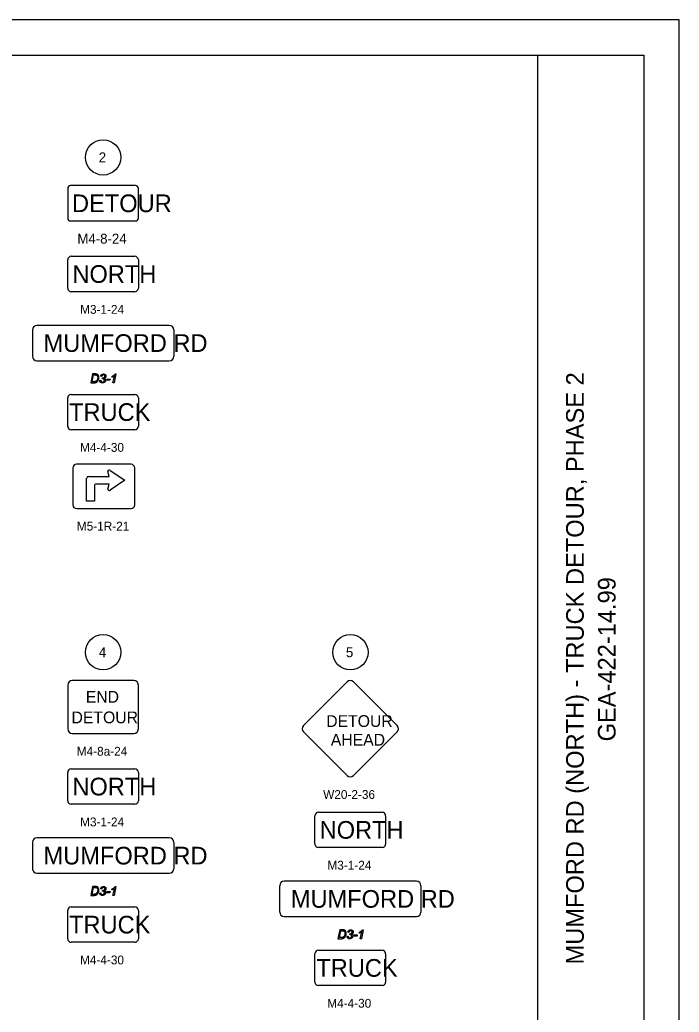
# Model space of a CAD drawing. Extents: x -0.3 to 34, y 0 to 22.
# Drawn here: x 24.67 to 34, y 7.96 to 22 of the extents above; entities that cross this region are included whole.
import ezdxf

# ---------------------------------------------------------------- set-up
doc = ezdxf.new("R2010")
doc.units = 0
for name, color, linetype in [('GM_X_County', 7, 'Continuous'), ('GM_X_Minor_Lake_Text', 7, 'Continuous'), ('GM_X_Minor_River_Text', 7, 'Continuous'), ('GM_X_Section', 7, 'Continuous'), ('GM_X_Township', 7, 'Continuous')]:
    doc.layers.add(name, color=color, linetype=linetype)

msp = doc.modelspace()

# ---------------------------------------------------------------- linework, layer by layer
at = {"layer": 'GM_X_County'}
msp.add_line((32, 0.5), (32, 21.5), dxfattribs=at)
msp.add_lwpolyline([(1.5, 21.5), (33.5, 21.5), (33.5, 0.5), (1.5, 0.5)], close=True, dxfattribs=at)
at = {"layer": 'GM_X_Minor_Lake_Text'}
for p, q in [((25.798, 16.899), (25.813, 16.901)), ((25.827, 16.956), (25.812, 16.959)), ((25.836, 16.924), (25.839, 16.937)), ((25.97, 16.944), (25.973, 16.958)), ((25.827, 9.706), (25.812, 9.709)), ((25.836, 9.674), (25.839, 9.687)), ((25.97, 9.694), (25.973, 9.708)), ((25.798, 9.649), (25.813, 9.651)), ((29.298, 9.036), (29.313, 9.038)), ((29.327, 9.094), (29.312, 9.097)), ((29.336, 9.061), (29.339, 9.074)), ((29.47, 9.082), (29.473, 9.096))]:
    msp.add_line(p, q, dxfattribs=at)
for points in [[(25.734, 16.991), (25.697, 16.991), (25.67, 16.866), (25.716, 16.866)], [(26.019, 16.991), (26.028, 16.991), (26.002, 16.866), (25.986, 16.866), (26.006, 16.96)], [(25.71, 16.88), (25.69, 16.88), (25.71, 16.977), (25.732, 16.977)], [(25.734, 9.741), (25.697, 9.741), (25.67, 9.616), (25.716, 9.616)], [(25.71, 9.63), (25.69, 9.63), (25.71, 9.727), (25.732, 9.727)], [(26.019, 9.741), (26.028, 9.741), (26.002, 9.616), (25.986, 9.616), (26.006, 9.71)], [(29.234, 9.128), (29.197, 9.128), (29.17, 9.003), (29.216, 9.003)], [(29.519, 9.129), (29.528, 9.129), (29.502, 9.003), (29.486, 9.003), (29.506, 9.098)], [(29.21, 9.018), (29.19, 9.018), (29.21, 9.114), (29.232, 9.114)]]:
    msp.add_lwpolyline(points, dxfattribs=at)
for points in [[(25.894, 16.903), (25.897, 16.919), (25.944, 16.919), (25.941, 16.903)], [(25.894, 9.653), (25.897, 9.669), (25.944, 9.669), (25.941, 9.653)], [(29.394, 9.041), (29.397, 9.056), (29.444, 9.056), (29.441, 9.041)]]:
    msp.add_lwpolyline(points, close=True, dxfattribs=at)
for centre in [(25.846, 20.055), (25.846, 13.055), (29.346, 13.055)]:
    msp.add_circle(centre, 0.25, dxfattribs=at)
for points in [[(25.755, 16.989), (25.748, 16.991), (25.734, 16.991)], [(25.772, 16.98), (25.765, 16.986), (25.755, 16.989)], [(25.827, 16.983), (25.837, 16.991), (25.852, 16.991)], [(25.852, 16.991), (25.867, 16.991), (25.877, 16.982)], [(26.012, 16.983), (26.016, 16.987), (26.019, 16.991)], [(25.734, 16.883), (25.723, 16.88), (25.71, 16.88)], [(25.716, 16.866), (25.728, 16.866), (25.736, 16.868)], [(25.732, 16.977), (25.745, 16.977), (25.751, 16.975)], [(25.745, 16.887), (25.74, 16.884), (25.734, 16.883)], [(25.736, 16.868), (25.747, 16.87), (25.755, 16.876)], [(25.756, 16.897), (25.751, 16.891), (25.745, 16.887)], [(25.751, 16.975), (25.76, 16.972), (25.765, 16.964)], [(25.755, 16.876), (25.763, 16.881), (25.771, 16.891)], [(25.766, 16.916), (25.762, 16.906), (25.756, 16.897)], [(25.765, 16.964), (25.77, 16.956), (25.77, 16.941)], [(25.77, 16.941), (25.77, 16.927), (25.766, 16.916)], [(25.771, 16.891), (25.778, 16.9), (25.783, 16.912)], [(25.783, 16.963), (25.78, 16.973), (25.772, 16.98)], [(25.787, 16.94), (25.787, 16.952), (25.783, 16.963)], [(25.783, 16.912), (25.787, 16.925), (25.787, 16.94)], [(25.81, 16.873), (25.8, 16.883), (25.798, 16.899)], [(25.837, 16.864), (25.82, 16.864), (25.81, 16.873)], [(25.812, 16.959), (25.816, 16.974), (25.827, 16.983)], [(25.813, 16.901), (25.815, 16.887), (25.821, 16.882)], [(25.821, 16.882), (25.827, 16.876), (25.836, 16.876)], [(25.836, 16.973), (25.829, 16.967), (25.827, 16.956)], [(25.851, 16.979), (25.842, 16.979), (25.836, 16.973)], [(25.841, 16.924), (25.84, 16.924), (25.836, 16.924)], [(25.836, 16.876), (25.848, 16.876), (25.856, 16.884)], [(25.868, 16.876), (25.855, 16.864), (25.837, 16.864)], [(25.839, 16.937), (25.841, 16.936), (25.843, 16.936)], [(25.858, 16.918), (25.852, 16.924), (25.841, 16.924)], [(25.843, 16.936), (25.856, 16.936), (25.864, 16.943)], [(25.865, 16.973), (25.859, 16.979), (25.851, 16.979)], [(25.856, 16.884), (25.864, 16.892), (25.864, 16.903)], [(25.864, 16.903), (25.864, 16.912), (25.858, 16.918)], [(25.864, 16.943), (25.871, 16.949), (25.871, 16.959)], [(25.871, 16.959), (25.871, 16.967), (25.865, 16.973)], [(25.881, 16.942), (25.876, 16.935), (25.865, 16.93)], [(25.865, 16.93), (25.873, 16.925), (25.876, 16.919)], [(25.88, 16.905), (25.88, 16.888), (25.868, 16.876)], [(25.876, 16.919), (25.88, 16.913), (25.88, 16.905)], [(25.877, 16.982), (25.886, 16.973), (25.886, 16.959)], [(25.886, 16.959), (25.886, 16.949), (25.881, 16.942)], [(26.006, 16.96), (25.993, 16.95), (25.97, 16.944)], [(25.973, 16.958), (25.984, 16.963), (25.995, 16.97)], [(25.995, 16.97), (26.007, 16.978), (26.012, 16.983)], [(25.732, 9.727), (25.745, 9.727), (25.751, 9.725)], [(25.755, 9.739), (25.748, 9.741), (25.734, 9.741)], [(25.751, 9.725), (25.76, 9.722), (25.765, 9.714)], [(25.772, 9.73), (25.765, 9.736), (25.755, 9.739)], [(25.765, 9.714), (25.77, 9.706), (25.77, 9.691)], [(25.77, 9.691), (25.77, 9.677), (25.766, 9.666)], [(25.783, 9.713), (25.78, 9.723), (25.772, 9.73)], [(25.787, 9.69), (25.787, 9.702), (25.783, 9.713)], [(25.783, 9.662), (25.787, 9.675), (25.787, 9.69)], [(25.812, 9.709), (25.816, 9.724), (25.827, 9.733)], [(25.827, 9.733), (25.837, 9.741), (25.852, 9.741)], [(25.836, 9.723), (25.829, 9.717), (25.827, 9.706)], [(25.851, 9.729), (25.842, 9.729), (25.836, 9.723)], [(25.839, 9.687), (25.841, 9.686), (25.843, 9.686)], [(25.843, 9.686), (25.856, 9.686), (25.864, 9.693)], [(25.865, 9.723), (25.859, 9.729), (25.851, 9.729)], [(25.852, 9.741), (25.867, 9.741), (25.877, 9.732)], [(25.864, 9.693), (25.871, 9.699), (25.871, 9.709)], [(25.871, 9.709), (25.871, 9.717), (25.865, 9.723)], [(25.881, 9.692), (25.876, 9.685), (25.865, 9.68)], [(25.877, 9.732), (25.886, 9.723), (25.886, 9.709)], [(25.886, 9.709), (25.886, 9.699), (25.881, 9.692)], [(26.006, 9.71), (25.993, 9.7), (25.97, 9.694)], [(25.973, 9.708), (25.984, 9.713), (25.995, 9.72)], [(25.995, 9.72), (26.007, 9.728), (26.012, 9.733)], [(26.012, 9.733), (26.016, 9.737), (26.019, 9.741)], [(25.734, 9.633), (25.723, 9.63), (25.71, 9.63)], [(25.716, 9.616), (25.728, 9.616), (25.736, 9.618)], [(25.745, 9.637), (25.74, 9.634), (25.734, 9.633)], [(25.736, 9.618), (25.747, 9.62), (25.755, 9.626)], [(25.756, 9.647), (25.751, 9.641), (25.745, 9.637)], [(25.755, 9.626), (25.763, 9.631), (25.771, 9.641)], [(25.766, 9.666), (25.762, 9.656), (25.756, 9.647)], [(25.771, 9.641), (25.778, 9.65), (25.783, 9.662)], [(25.81, 9.623), (25.8, 9.633), (25.798, 9.649)], [(25.837, 9.614), (25.82, 9.614), (25.81, 9.623)], [(25.813, 9.651), (25.815, 9.637), (25.821, 9.632)], [(25.821, 9.632), (25.827, 9.626), (25.836, 9.626)], [(25.841, 9.674), (25.84, 9.674), (25.836, 9.674)], [(25.836, 9.626), (25.848, 9.626), (25.856, 9.634)], [(25.868, 9.626), (25.855, 9.614), (25.837, 9.614)], [(25.858, 9.668), (25.852, 9.674), (25.841, 9.674)], [(25.856, 9.634), (25.864, 9.642), (25.864, 9.653)], [(25.864, 9.653), (25.864, 9.662), (25.858, 9.668)], [(25.865, 9.68), (25.873, 9.675), (25.876, 9.669)], [(25.88, 9.655), (25.88, 9.638), (25.868, 9.626)], [(25.876, 9.669), (25.88, 9.663), (25.88, 9.655)], [(29.255, 9.127), (29.248, 9.128), (29.234, 9.128)], [(29.272, 9.117), (29.265, 9.124), (29.255, 9.127)], [(29.327, 9.121), (29.337, 9.129), (29.352, 9.129)], [(29.352, 9.129), (29.367, 9.129), (29.377, 9.12)], [(29.512, 9.121), (29.516, 9.124), (29.519, 9.129)], [(29.234, 9.02), (29.223, 9.018), (29.21, 9.018)], [(29.216, 9.003), (29.228, 9.003), (29.236, 9.005)], [(29.232, 9.114), (29.245, 9.114), (29.251, 9.112)], [(29.245, 9.025), (29.24, 9.022), (29.234, 9.02)], [(29.236, 9.005), (29.247, 9.008), (29.255, 9.013)], [(29.256, 9.035), (29.251, 9.028), (29.245, 9.025)], [(29.251, 9.112), (29.26, 9.11), (29.265, 9.102)], [(29.255, 9.013), (29.263, 9.019), (29.271, 9.028)], [(29.266, 9.054), (29.262, 9.043), (29.256, 9.035)], [(29.265, 9.102), (29.27, 9.093), (29.27, 9.078)], [(29.27, 9.078), (29.27, 9.065), (29.266, 9.054)], [(29.271, 9.028), (29.278, 9.037), (29.283, 9.05)], [(29.283, 9.1), (29.28, 9.11), (29.272, 9.117)], [(29.287, 9.077), (29.287, 9.09), (29.283, 9.1)], [(29.283, 9.05), (29.287, 9.062), (29.287, 9.077)], [(29.31, 9.011), (29.3, 9.02), (29.298, 9.036)], [(29.337, 9.001), (29.32, 9.001), (29.31, 9.011)], [(29.312, 9.097), (29.316, 9.112), (29.327, 9.121)], [(29.313, 9.038), (29.315, 9.025), (29.321, 9.019)], [(29.321, 9.019), (29.327, 9.014), (29.336, 9.014)], [(29.336, 9.111), (29.329, 9.105), (29.327, 9.094)], [(29.351, 9.117), (29.342, 9.117), (29.336, 9.111)], [(29.341, 9.062), (29.34, 9.062), (29.336, 9.061)], [(29.336, 9.014), (29.348, 9.014), (29.356, 9.022)], [(29.368, 9.014), (29.355, 9.001), (29.337, 9.001)], [(29.339, 9.074), (29.341, 9.074), (29.343, 9.074)], [(29.358, 9.056), (29.352, 9.062), (29.341, 9.062)], [(29.343, 9.074), (29.356, 9.074), (29.364, 9.08)], [(29.365, 9.111), (29.359, 9.117), (29.351, 9.117)], [(29.356, 9.022), (29.364, 9.03), (29.364, 9.041)], [(29.364, 9.041), (29.364, 9.05), (29.358, 9.056)], [(29.364, 9.08), (29.371, 9.087), (29.371, 9.096)], [(29.371, 9.096), (29.371, 9.105), (29.365, 9.111)], [(29.381, 9.08), (29.376, 9.072), (29.365, 9.067)], [(29.365, 9.067), (29.373, 9.063), (29.376, 9.057)], [(29.38, 9.043), (29.38, 9.026), (29.368, 9.014)], [(29.376, 9.057), (29.38, 9.051), (29.38, 9.043)], [(29.377, 9.12), (29.386, 9.11), (29.386, 9.097)], [(29.386, 9.097), (29.386, 9.087), (29.381, 9.08)], [(29.506, 9.098), (29.493, 9.088), (29.47, 9.082)], [(29.473, 9.096), (29.484, 9.1), (29.495, 9.108)], [(29.495, 9.108), (29.507, 9.115), (29.512, 9.121)]]:
    msp.add_open_spline(points, degree=2, dxfattribs=at)
at = {"layer": 'GM_X_Minor_River_Text'}
for p, q in [((25.345, 18.205), (25.345, 18.605)), ((25.395, 18.655), (26.295, 18.655)), ((26.345, 18.605), (26.345, 18.205)), ((26.295, 18.155), (25.395, 18.155)), ((25.345, 16.252), (25.345, 16.652)), ((25.395, 16.702), (26.295, 16.702)), ((26.345, 16.652), (26.345, 16.252)), ((26.295, 16.202), (25.395, 16.202)), ((25.418, 15.663), (25.418, 15.138)), ((26.243, 15.713), (25.468, 15.713)), ((25.934, 15.541), (25.913, 15.612)), ((25.948, 15.626), (26.152, 15.487)), ((26.293, 15.138), (26.293, 15.663)), ((25.613, 15.19), (25.613, 15.518)), ((25.637, 15.541), (25.934, 15.541)), ((25.637, 15.541), (25.637, 15.541)), ((26.152, 15.487), (25.948, 15.347)), ((25.723, 15.416), (25.723, 15.19)), ((25.934, 15.432), (25.738, 15.432)), ((25.913, 15.362), (25.934, 15.432)), ((25.723, 15.19), (25.613, 15.19)), ((25.468, 15.088), (26.243, 15.088)), ((25.395, 11.405), (26.295, 11.405)), ((25.345, 10.955), (25.345, 11.355)), ((26.345, 11.355), (26.345, 10.955)), ((26.295, 10.905), (25.395, 10.905)), ((28.845, 10.342), (28.845, 10.742)), ((28.895, 10.792), (29.795, 10.792)), ((29.845, 10.742), (29.845, 10.342)), ((29.795, 10.292), (28.895, 10.292)), ((25.395, 9.452), (26.295, 9.452)), ((25.345, 9.002), (25.345, 9.402)), ((26.345, 9.402), (26.345, 9.002)), ((26.295, 8.952), (25.395, 8.952)), ((28.845, 8.39), (28.845, 8.79)), ((28.895, 8.84), (29.795, 8.84)), ((29.845, 8.79), (29.845, 8.39)), ((29.795, 8.34), (28.895, 8.34))]:
    msp.add_line(p, q, dxfattribs=at)
for points in [[(26.305, 19.655), (25.385, 19.655)], [(25.345, 19.615), (25.345, 19.195)], [(26.345, 19.195), (26.345, 19.615)], [(25.385, 19.155), (26.305, 19.155)], [(24.845, 17.616), (24.845, 17.241)], [(26.783, 17.678), (24.908, 17.678)], [(26.845, 17.616), (26.845, 17.241)], [(24.908, 17.178), (26.783, 17.178)], [(26.28, 12.655), (25.41, 12.655)], [(28.682, 12.018), (29.301, 12.636)], [(29.389, 12.636), (30.008, 12.018)], [(25.345, 12.59), (25.345, 11.97)], [(26.345, 11.97), (26.345, 12.59)], [(25.41, 11.905), (26.28, 11.905)], [(29.301, 11.311), (28.682, 11.929)], [(30.008, 11.929), (29.389, 11.311)], [(26.783, 10.428), (24.908, 10.428)], [(24.845, 10.366), (24.845, 9.991)], [(26.845, 10.366), (26.845, 9.991)], [(24.908, 9.928), (26.783, 9.928)], [(28.345, 9.753), (28.345, 9.378)], [(30.283, 9.816), (28.408, 9.816)], [(30.345, 9.753), (30.345, 9.378)], [(28.408, 9.316), (30.283, 9.316)]]:
    msp.add_lwpolyline(points, dxfattribs=at)
for centre, radius, start, end in [((25.385, 19.615), 0.04, 90, 180), ((26.305, 19.615), 0.04, 0, 90), ((25.385, 19.195), 0.04, 180, 270), ((26.305, 19.195), 0.04, 270, 0), ((25.395, 18.605), 0.05, 90, 180), ((26.295, 18.605), 0.05, 0, 90), ((25.395, 18.205), 0.05, 180, 270), ((26.295, 18.205), 0.05, 270, 0), ((24.908, 17.616), 0.0625, 90, 180), ((26.783, 17.616), 0.0625, 0, 90), ((24.908, 17.241), 0.0625, 180, 270), ((26.783, 17.241), 0.0625, 270, 0), ((25.395, 16.652), 0.05, 90, 180), ((26.295, 16.652), 0.05, 0, 90), ((25.395, 16.252), 0.05, 180, 270), ((26.295, 16.252), 0.05, 270, 360), ((25.468, 15.663), 0.05, 90, 180), ((25.934, 15.612), 0.0209, 45.0001, 179.9983), ((26.243, 15.663), 0.05, 0, 90), ((25.637, 15.518), 0.0234, 90, 180), ((25.738, 15.416), 0.0156, 90, 180), ((25.934, 15.362), 0.0209, 179.9983, 314.9999), ((25.468, 15.138), 0.05, 180, 270), ((26.243, 15.138), 0.05, 270, 0), ((25.41, 12.59), 0.065, 90, 180), ((26.28, 12.59), 0.065, 0, 90), ((29.345, 12.592), 0.0625, 45, 135), ((25.41, 11.97), 0.065, 180, 270), ((26.28, 11.97), 0.065, 270, 0), ((28.727, 11.973), 0.0625, 135, 225), ((29.964, 11.973), 0.0625, 315, 45), ((25.395, 11.355), 0.05, 90, 180), ((26.295, 11.355), 0.05, 0, 90), ((29.345, 11.355), 0.0625, 225, 315), ((25.395, 10.955), 0.05, 180, 270), ((26.295, 10.955), 0.05, 270, 0), ((28.895, 10.742), 0.05, 90, 180), ((29.795, 10.742), 0.05, 0, 90), ((24.908, 10.366), 0.0625, 90, 180), ((26.783, 10.366), 0.0625, 0, 90), ((28.895, 10.342), 0.05, 180, 270), ((29.795, 10.342), 0.05, 270, 0), ((24.908, 9.991), 0.0625, 180, 270), ((26.783, 9.991), 0.0625, 270, 0), ((28.408, 9.753), 0.0625, 90, 180), ((30.283, 9.753), 0.0625, 0, 90), ((25.395, 9.402), 0.05, 90, 180), ((26.295, 9.402), 0.05, 0, 90), ((28.408, 9.378), 0.0625, 180, 270), ((30.283, 9.378), 0.0625, 270, 0), ((25.395, 9.002), 0.05, 180, 270), ((26.295, 9.002), 0.05, 270, 360), ((28.895, 8.79), 0.05, 90, 180), ((29.795, 8.79), 0.05, 0, 90), ((28.895, 8.39), 0.05, 180, 270), ((29.795, 8.39), 0.05, 270, 360)]:
    msp.add_arc(centre, radius, start, end, dxfattribs=at)
at = {"layer": 'GM_X_Section'}
msp.add_lwpolyline([(0, 0), (34, 0), (34, 22), (0, 22)], close=True, dxfattribs=at)

# ---------------------------------------------------------------- texts
at = {"layer": 'GM_X_Minor_Lake_Text'}
for s, height, p in [('2', 0.14, (25.784, 19.985)), ('M4-8-24', 0.14, (25.482, 18.835)), ('M3-1-24', 0.125, (25.521, 17.842)), ('M4-4-30', 0.125, (25.519, 15.89)), ('M5-1R-21', 0.125, (25.474, 14.776)), ('4', 0.14, (25.786, 12.985)), ('5', 0.14, (29.283, 12.985)), ('M4-8a-24', 0.125, (25.473, 11.592)), ('W20-2-36', 0.125, (28.961, 10.98)), ('M3-1-24', 0.125, (25.521, 10.592)), ('M3-1-24', 0.125, (29.021, 9.98)), ('M4-4-30', 0.125, (25.519, 8.64)), ('M4-4-30', 0.125, (29.019, 8.027))]:
    msp.add_text(s, height=height, dxfattribs=at).set_placement(p)
at = {"layer": 'GM_X_Minor_River_Text'}
for s, height, p in [('DETOUR', 0.25, (25.406, 19.28)), ('NORTH', 0.25, (25.411, 18.28)), ('MUMFORD RD', 0.25, (25.003, 17.303)), ('TRUCK', 0.25, (25.364, 16.327)), ('END', 0.1667, (25.601, 12.341)), ('DETOUR', 0.1667, (25.399, 12.05)), ('DETOUR', 0.1667, (29.004, 11.998)), ('AHEAD', 0.1667, (29.069, 11.734)), ('NORTH', 0.25, (25.411, 11.03)), ('NORTH', 0.25, (28.911, 10.417)), ('MUMFORD RD', 0.25, (25.003, 10.053)), ('MUMFORD RD', 0.25, (28.503, 9.441)), ('TRUCK', 0.25, (25.364, 9.077)), ('TRUCK', 0.25, (28.864, 8.465))]:
    msp.add_text(s, height=height, dxfattribs=at).set_placement(p)
at = {"layer": 'GM_X_Township'}
for s, p in [('MUMFORD RD (NORTH) - TRUCK DETOUR, PHASE 2', (32.65, 8.639)), ('GEA-422-14.99', (33.1, 11.794))]:
    msp.add_text(s, height=0.25, rotation=90, dxfattribs=at).set_placement(p)

doc.saveas('drawing.dxf')
